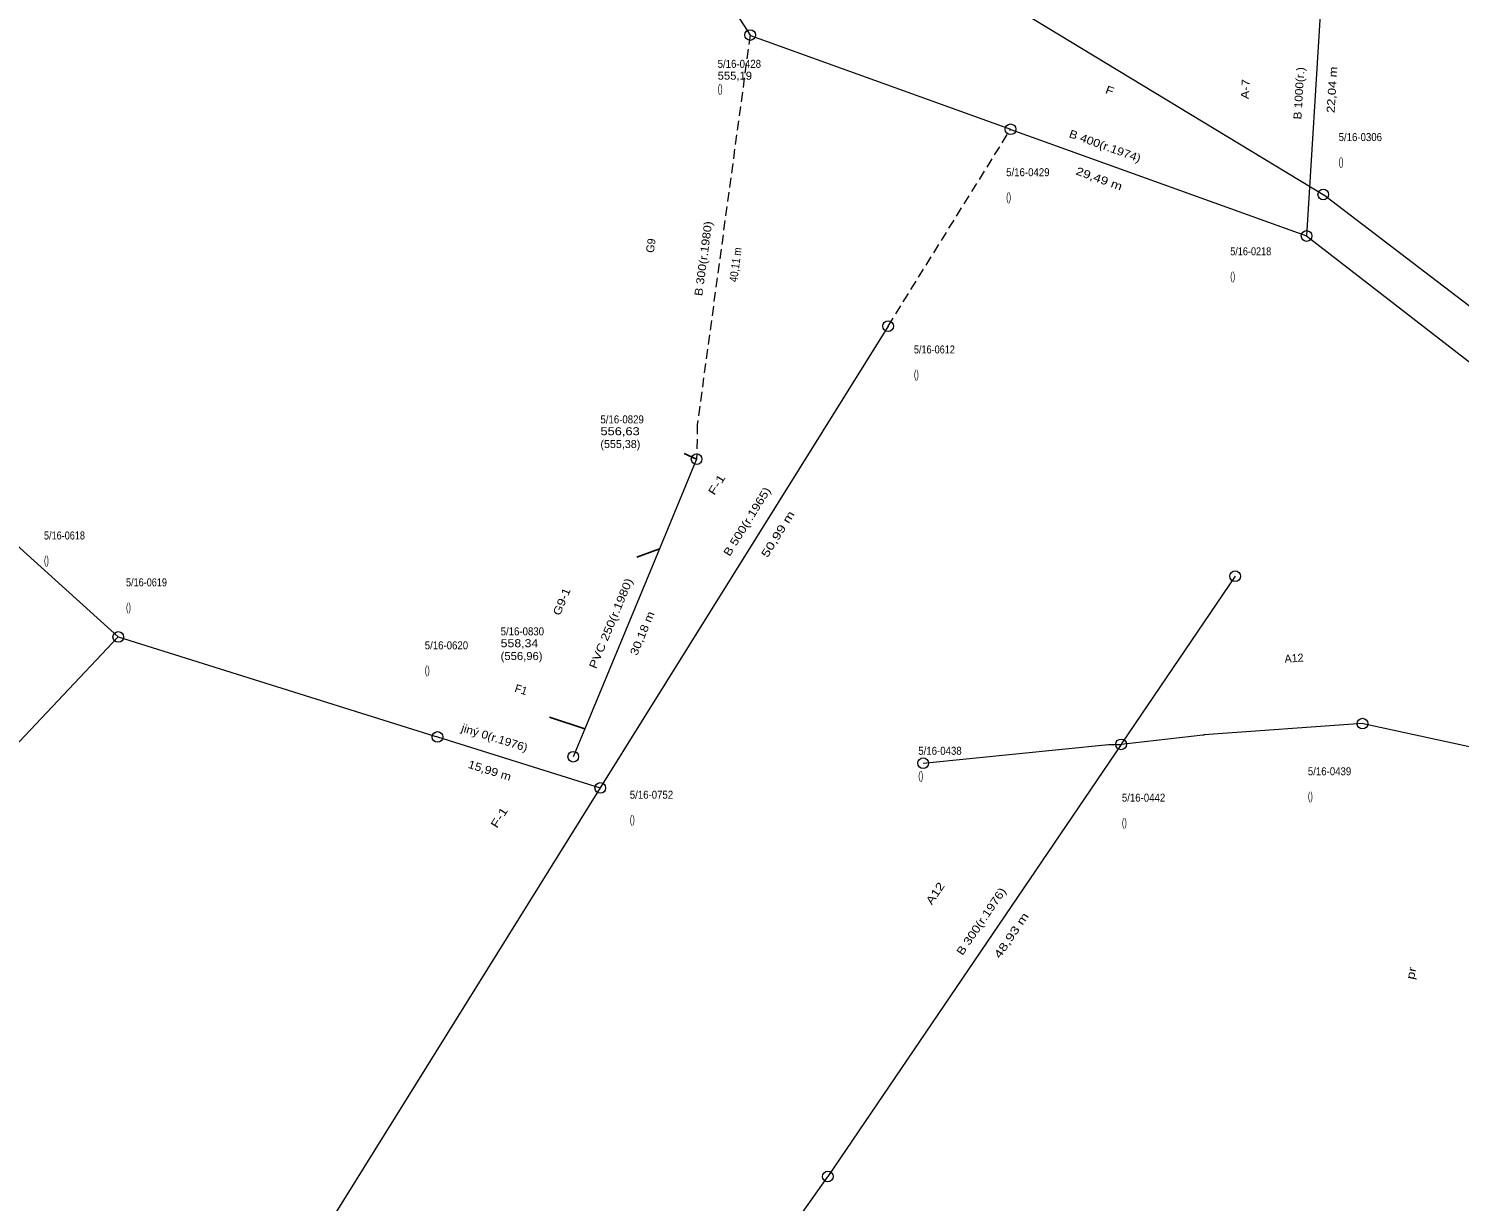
# Model space of a CAD drawing. Extents: x -710854 to -709799, y -1117012 to -1115891.
# Drawn here: x -710518.1 to -710384, y -1116613.4 to -1116503.5 of the extents above; entities that cross this region are included whole.
import ezdxf
from ezdxf.enums import TextEntityAlignment as Align

# ---------------------------------------------------------------- set-up
doc = ezdxf.new("R2010")
doc.units = 0
doc.header["$LTSCALE"] = 0.3
doc.linetypes.add('MEDIUM_DASHED', pattern=[4.5, 3, -1.5])
for name, color, linetype, lineweight in [('35', 7, 'Continuous', 25), ('36', 7, 'Continuous', 13), ('38', 7, 'Continuous', 13), ('44', 7, 'Continuous', 13)]:
    doc.layers.add(name, color=color, linetype=linetype, lineweight=lineweight)
doc.layers.add('48', color=7, linetype='Continuous')

msp = doc.modelspace()

# ---------------------------------------------------------------- linework, layer by layer
at = {"layer": '35'}
for p, q in [((-710455.46, -1116543.81), (-710456.64, -1116543.29)), ((-710458.937, -1116552.197), (-710461.066, -1116552.988)), ((-710465.935, -1116569.073), (-710469.25, -1116567.98))]:
    msp.add_line(p, q, dxfattribs=at)
at = {"layer": '36'}
msp.add_line((-710453.004, -1116484.913), (-710396.742, -1116519.013), dxfattribs=at)
msp.add_lwpolyline([(-710396.742, -1116519.013), (-710396.602, -1116519.097), (-710360.82, -1116546.41)], dxfattribs=at)
at = {"layer": '38', "linetype": 'MEDIUM_DASHED'}
msp.add_line((-710437.52, -1116531.35), (-710426.044, -1116512.903), dxfattribs=at)
at = {"layer": '38'}
for p, q in [((-710437.52, -1116531.35), (-710464.49, -1116574.62)), ((-710509.66, -1116560.47), (-710522.227, -1116573.746)), ((-710415.686, -1116570.534), (-710443.163, -1116611.02)), ((-710464.49, -1116574.62), (-710518.8, -1116661.74))]:
    msp.add_line(p, q, dxfattribs=at)
for points in [[(-710479.01, -1116460.54), (-710471.6, -1116471.29), (-710471.59, -1116471.305), (-710471.566, -1116471.343), (-710450.451, -1116504.072)], [(-710396.975, -1116500.905), (-710396.96, -1116500.95), (-710396.972, -1116501.151), (-710398.3, -1116522.9)], [(-710450.451, -1116504.072), (-710450.435, -1116504.097), (-710450.42, -1116504.12), (-710426.044, -1116512.903)], [(-710426.044, -1116512.903), (-710426.027, -1116512.909), (-710398.3, -1116522.9)], [(-710398.3, -1116522.9), (-710374.23, -1116541.52), (-710374.197, -1116541.54)], [(-710455.46, -1116543.81), (-710458.937, -1116552.197), (-710465.935, -1116569.073), (-710467.02, -1116571.69)], [(-710520.158, -1116550.954), (-710520.153, -1116550.959), (-710509.66, -1116560.47)], [(-710405, -1116554.78), (-710415.552, -1116570.337), (-710415.686, -1116570.534)], [(-710509.66, -1116560.47), (-710480.004, -1116569.759), (-710479.84, -1116569.81), (-710479.746, -1116569.839), (-710464.49, -1116574.62)], [(-710393.06, -1116568.59), (-710407.89, -1116569.65), (-710407.936, -1116569.655), (-710408.038, -1116569.665), (-710415.686, -1116570.534)], [(-710363.33, -1116575.03), (-710392.833, -1116568.639), (-710393.06, -1116568.59)], [(-710434.23, -1116572.3), (-710416.86, -1116570.552), (-710415.686, -1116570.534)], [(-710443.163, -1116611.02), (-710443.17, -1116611.03), (-710443.215, -1116611.093), (-710459.097, -1116633.494), (-710459.111, -1116633.513)]]:
    msp.add_lwpolyline(points, dxfattribs=at)
at = {"layer": '38', "linetype": 'MEDIUM_DASHED'}
msp.add_lwpolyline([(-710450.451, -1116504.072), (-710455.4, -1116540.58), (-710455.46, -1116543.81)], dxfattribs=at)
at = {"layer": '44'}
for centre in [(-710450.451, -1116504.072), (-710426.044, -1116512.903), (-710396.742, -1116519.013), (-710398.3, -1116522.9), (-710437.52, -1116531.35), (-710455.46, -1116543.81), (-710405, -1116554.78), (-710509.66, -1116560.47), (-710393.06, -1116568.59), (-710479.746, -1116569.839), (-710467.02, -1116571.69), (-710415.686, -1116570.534), (-710434.23, -1116572.3), (-710464.49, -1116574.62), (-710443.163, -1116611.02)]:
    msp.add_circle(centre, 0.5, dxfattribs=at)

# ---------------------------------------------------------------- texts
at = {"layer": '48'}
for s, width, p in [('5/16-0428', 0.9, (-710453.492, -1116507.144)), ('555,19 ', 1.05, (-710453.492, -1116508.254)), ('()', 0.7, (-710453.492, -1116509.454)), ('5/16-0306', 0.9, (-710395.303, -1116514.006)), ('()', 0.7, (-710395.303, -1116516.316)), ('5/16-0429', 0.9, (-710426.456, -1116517.299)), ('()', 0.7, (-710426.456, -1116519.609)), ('5/16-0218', 0.85, (-710405.458, -1116524.71)), ('()', 0.7, (-710405.458, -1116527.02)), ('5/16-0612', 0.85, (-710435.102, -1116533.905)), ('()', 0.7, (-710435.102, -1116536.215)), ('5/16-0829', 0.9, (-710464.477, -1116540.458)), ('556,63 ', 1.2, (-710464.477, -1116541.568)), ('5/16-0618', 0.85, (-710516.623, -1116551.335)), ('()', 0.7, (-710516.623, -1116553.645)), ('5/16-0619', 0.85, (-710508.937, -1116555.726)), ('()', 0.7, (-710508.937, -1116558.036)), ('5/16-0830', 0.9, (-710473.828, -1116560.319)), ('5/16-0620', 0.9, (-710480.94, -1116561.628)), ('558,34 ', 1.15, (-710473.828, -1116561.429)), ('(556,96)', 1.05, (-710473.828, -1116562.629)), ('()', 0.7, (-710480.94, -1116563.938)), ('5/16-0438', 0.9, (-710434.691, -1116571.509)), ('()', 0.7, (-710434.691, -1116573.819)), ('5/16-0439', 0.9, (-710398.185, -1116573.43)), ('5/16-0752', 0.9, (-710461.727, -1116575.626)), ('5/16-0442', 0.9, (-710415.614, -1116575.901)), ('()', 0.7, (-710398.185, -1116575.74)), ('()', 0.7, (-710461.727, -1116577.936)), ('()', 0.7, (-710415.614, -1116578.211))]:
    msp.add_text(s, height=0.75, dxfattribs=dict(at, width=width)).set_placement(p)
for s, rotation, width, p in [('B 1000(r.)', 86.51, 1.1, (-710398.6468, -1116509.5458)), ('22,04 m', 86.51, 1.2, (-710395.5514, -1116509.2218)), ('F', 340.18, 1.25, (-710416.8696, -1116509.6188)), ('A-7', 86.51, 1.2, (-710403.6725, -1116509.1588)), ('B 400(r.1974)', 340.18, 1.15, (-710417.3166, -1116514.815)), ('29,49 m', 340.18, 1.25, (-710417.8686, -1116517.8795)), ('B 300(r.1980)', 82.28, 1.15, (-710454.4662, -1116525.0649)), ('40,11 m', 82.28, 0.9, (-710451.4476, -1116525.6454)), ('F-1', 58.06, 1.35, (-710453.2676, -1116546.3974)), ('B 500(r.1965)', 58.06, 1.2, (-710450.4215, -1116549.8554)), ('50,99 m', 58.06, 1.35, (-710447.5341, -1116551.0279)), ('PVC 250(r.1980)', 67.48, 1.2, (-710463.1535, -1116559.3371)), ('G9-1', 67.48, 1.2, (-710467.763, -1116557.2971)), ('30,18 m', 67.48, 1.2, (-710460.2164, -1116560.2691)), ('jiný 0(r.1976)', 342.6, 1.1, (-710474.5076, -1116570.265)), ('15,99 m', 342.6, 1.15, (-710474.9646, -1116573.3381)), ('F-1', 58.06, 1.35, (-710473.6446, -1116577.5854)), ('A12', 55.84, 1.25, (-710432.7964, -1116584.7031)), ('B 300(r.1976)', 55.84, 1.2, (-710428.483, -1116587.3236)), ('48,93 m', 55.84, 1.35, (-710425.6674, -1116588.6411)), ('pr', 77.87, 1.3, (-710388.1292, -1116592.0418))]:
    msp.add_text(s, height=0.75, rotation=rotation, dxfattribs=dict(at, width=width)).set_placement(p, align=Align.CENTER)
for s, rotation, p in [('G9', 82.28, (-710459.3887, -1116523.8504)), ('A12', 4.09, (-710399.4542, -1116562.831)), ('F1', 342.6, (-710472.0196, -1116565.7626))]:
    msp.add_text(s, height=0.75, rotation=rotation, dxfattribs=at).set_placement(p, align=Align.CENTER)
msp.add_text('(555,38)', height=0.75, dxfattribs=at).set_placement((-710464.477, -1116542.768))

doc.saveas('drawing.dxf')
